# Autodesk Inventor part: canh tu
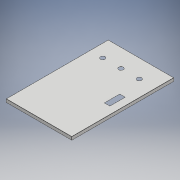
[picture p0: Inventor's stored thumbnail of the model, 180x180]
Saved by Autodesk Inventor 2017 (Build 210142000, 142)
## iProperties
Created: 2022-04
Part Number: canh tu
Material: Generic
Document SubType Name: Sheet Metal
Designer: phat
Density: 1 g/cm^3
Sheet Metal Rule: Default_mm
Appearance: Default
Author: phat
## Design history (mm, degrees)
node "Face1"
  sketch "Sketch1"
    geometry: L1 (-180, 280)-(180, 280); L2 (180, 280)-(180, -280); L3 (180, -280)-(-180, -280); L4 (-180, -280)-(-180, 280); L5 (-180, 280)-(180, -280); L6 (180, 280)-(-180, -280); 1 further point
    constraints: 12 end point, 2 midpoint, 2 parallel, 1 horizontal, 1 perpendicular
    dimensions: "d0" = 360 distance of L2.end L3.end; "d1" = 560 distance of L1.end L2.end
node "Flange1"
sketch "Sketch3"
  geometry: L1 (109, 54)-(139, 54); L2 (139, 54)-(139, -30); L3 (139, -30)-(109, -30); L4 (109, -30)-(109, 54); L5 (179, 279)-(-179, 279) reference; L6 (179, -279)-(179, 279) reference; L7 (-179, 279)-(-179, -279) reference; C1 r 12.5 at (-109, 179); 2 further points
  constraints: 8 end point, 2 parallel, 1 centre point, 1 coincident, 1 horizontal, 1 perpendicular
  dimensions: "d13" = 30 distance of L2.end L3.end; "d14" = 84 distance of L1.end L2.end; "d15" = 225 distance between parallel lines of L1 L5; "d16" = 70 distance between parallel lines of L6 L4; "d17" = 70 distance from line of L7 point (-109, 179); "d18" = 100 distance from line of L5 point (-109, 179); "d19" = 25 diameter of C1
cut "Cut1" sketch "Sketch3" dims "d20" = 0.5 (= Thickness), "d21" = 0
pattern_linear "Rectangular Pattern1" dims "d24" = 100
body "Solid1"
face "Plate1" dims "Thickness" = 0.5
sketch "Sketch2"
  geometry: L1 through (180, 0) direction (-1, 0); L2 through (0, -8.5) direction (0, -1); L3 (0, -17)-(360, -17); L4 (360, -17)-(360, 0)
  constraints: 6 end point, 1 horizontal, 1 perpendicular, 1 vertical
face "Plate2" dims "d3" = 0.5 (= BendReliefWidth), "d4" = 0.25 (= BendReliefDepth), "d5" = 1 (= MinimumRemnant), "d6" = 0.5 (= BendRadius), "d7" = 17, "d8" = 90 deg, "d9" = 0.5 (= BendRadius), "d10" = 2 (= CornerReliefSize), "d11" = 0.5 (= GapSize), "d12" = 0.5 (= JacobiRadiusSize), "SeamGap" = 0.01, "Thickness" = 0.5
bend "Bend1" dims "d3" = 0.5 (= BendReliefWidth), "d4" = 0.25 (= BendReliefDepth), "d5" = 1 (= MinimumRemnant), "d6" = 0.5 (= BendRadius), "d7" = 17, "d8" = 90 deg, "d9" = 0.5 (= BendRadius), "SeamGap" = 0.01, "Thickness" = 0.5
feature "Corner1" dims "d7" = 17, "d8" = 90 deg, "d10" = 2 (= CornerReliefSize), "d11" = 0.5 (= GapSize), "d12" = 0.5 (= JacobiRadiusSize)
other parameters: "BendRadius" = 0.5 (= Thickness), "BendReliefWidth" = 0.5 (= Thickness), "BendReliefDepth" = 0.25 (= 0.5 x Thickness), "CornerReliefSize" = 2 (= 4 x Thickness), "MinimumRemnant" = 1 (= 2 x Thickness), "TransitionRadius" = 0.5 (= BendRadius), "JacobiRadiusSize" = 0.5 (= BendRadius), "GapSize" = 0.5 (= Thickness), "d2" = 0.5 (= BendRadius)
